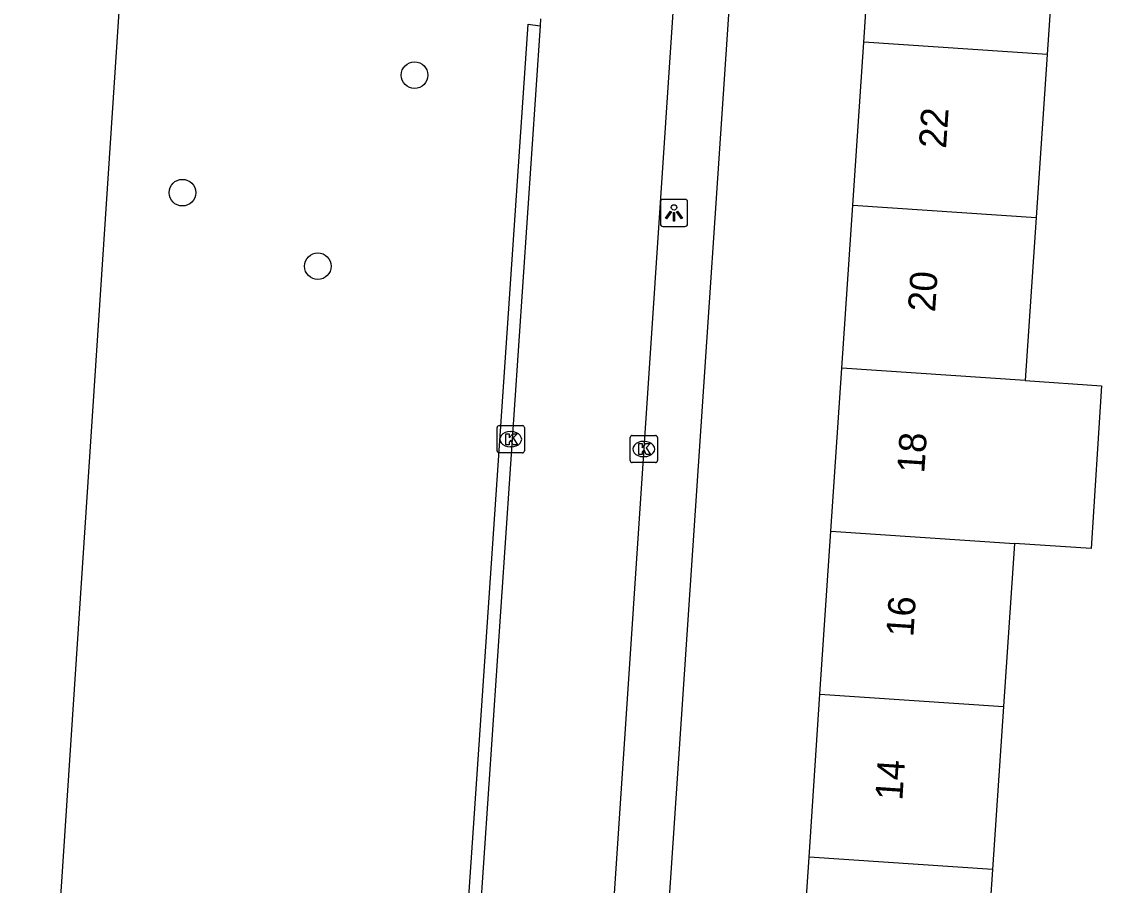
# Model space of a CAD drawing. Extents: x 161848 to 162726, y 385382 to 386521.
# Drawn here: x 161938.07 to 161977.75, y 385931.43 to 385963.18 of the extents above; entities that cross this region are included whole.
import ezdxf

# ---------------------------------------------------------------- set-up
doc = ezdxf.new("R2010")
doc.units = 0
for name, color, linetype in [('IMGEO_Berm_groen', 7, 'Continuous'), ('IMGEO_Boom', 7, 'Continuous'), ('IMGEO_Kolk', 7, 'Continuous'), ('IMGEO_Lichtpunt', 7, 'Continuous'), ('IMGEO_Pand', 7, 'Continuous'), ('IMGEO_Pand_nummerreeks', 7, 'Continuous'), ('IMGEO_Rijbaan_lokaal_open', 7, 'Continuous'), ('IMGEO_Verkeerseiland_open', 7, 'Continuous'), ('IMGEO_Voetpad_open', 7, 'Continuous')]:
    doc.layers.add(name, color=color, linetype=linetype)

msp = doc.modelspace()

# ---------------------------------------------------------------- linework, layer by layer
at = {"layer": 'IMGEO_Berm_groen'}
msp.add_lwpolyline([(161936.046, 385878.605), (161941.769, 385965.23)], dxfattribs=at)
at = {"layer": 'IMGEO_Boom'}
for centre in [(161952.514, 385961.213), (161943.984, 385956.893), (161948.961, 385954.19)]:
    msp.add_circle(centre, 0.489, dxfattribs=at)
at = {"layer": 'IMGEO_Kolk'}
for p, q in [((161955.546, 385947.405), (161955.546, 385948.257)), ((161955.621, 385948.331), (161956.473, 385948.331)), ((161956.034, 385948.111), (161956.059, 385948.111)), ((161956.547, 385948.257), (161956.547, 385947.405)), ((161960.435, 385947.046), (161960.435, 385947.898)), ((161960.51, 385947.972), (161961.362, 385947.972)), ((161960.923, 385947.752), (161960.948, 385947.752)), ((161961.436, 385947.898), (161961.436, 385947.046)), ((161956.473, 385947.331), (161955.621, 385947.331)), ((161956.057, 385947.551), (161956.032, 385947.551)), ((161961.362, 385946.972), (161960.51, 385946.972)), ((161960.946, 385947.192), (161960.921, 385947.192))]:
    msp.add_line(p, q, dxfattribs=at)
for points in [[(161955.546, 385947.405), (161955.546, 385948.257)], [(161955.621, 385948.331), (161956.473, 385948.331)], [(161955.867, 385948.031), (161955.99, 385948.031), (161955.99, 385947.88), (161956.12, 385948.031), (161956.284, 385948.031), (161956.138, 385947.88), (161956.291, 385947.631), (161956.139, 385947.631), (161956.054, 385947.795), (161955.99, 385947.728), (161955.99, 385947.631), (161955.867, 385947.631), (161955.867, 385948.031)], [(161956.547, 385948.257), (161956.547, 385947.405)], [(161960.435, 385947.046), (161960.435, 385947.898)], [(161960.51, 385947.972), (161961.362, 385947.972)], [(161960.756, 385947.672), (161960.879, 385947.672), (161960.879, 385947.521), (161961.009, 385947.672), (161961.173, 385947.672), (161961.027, 385947.521), (161961.18, 385947.272), (161961.028, 385947.272), (161960.943, 385947.436), (161960.879, 385947.369), (161960.879, 385947.272), (161960.756, 385947.272), (161960.756, 385947.672)], [(161961.436, 385947.898), (161961.436, 385947.046)], [(161956.473, 385947.331), (161955.621, 385947.331)], [(161961.362, 385946.972), (161960.51, 385946.972)]]:
    msp.add_lwpolyline(points, dxfattribs=at)
for centre, start, end in [((161955.623, 385948.255), 91.552, 178.448), ((161955.623, 385948.255), 91.552, 178.448), ((161956.471, 385948.255), 1.552, 88.448), ((161956.471, 385948.255), 1.552, 88.448), ((161960.512, 385947.896), 91.552, 178.448), ((161960.512, 385947.896), 91.552, 178.448), ((161961.36, 385947.896), 1.552, 88.448), ((161961.36, 385947.896), 1.552, 88.448), ((161955.623, 385947.407), 181.552, 268.448), ((161955.623, 385947.407), 181.552, 268.448), ((161956.471, 385947.407), 271.552, 358.448), ((161956.471, 385947.407), 271.552, 358.448), ((161960.512, 385947.048), 181.552, 268.448), ((161960.512, 385947.048), 181.552, 268.448), ((161961.36, 385947.048), 271.552, 358.448), ((161961.36, 385947.048), 271.552, 358.448)]:
    msp.add_arc(centre, 0.0765, start, end, dxfattribs=at)
for centre, major_axis, ratio, start_param, end_param in [((161956.033, 385947.831), (-0.387, 0.002), 0.722429, 4.712389, 7.853982), ((161956.058, 385947.831), (-0.39, 0.002), 0.717154, 1.570796, 4.712389), ((161960.922, 385947.472), (-0.387, 0.002), 0.722429, 4.712389, 7.853982), ((161960.947, 385947.472), (-0.39, 0.002), 0.717154, 1.570796, 4.712389)]:
    msp.add_ellipse(centre, major_axis=major_axis, ratio=ratio, start_param=start_param, end_param=end_param, dxfattribs=at)
at = {"layer": 'IMGEO_Lichtpunt'}
for p, q in [((161961.546, 385956.553), (161961.546, 385955.746)), ((161961.546, 385956.553), (161961.546, 385955.746)), ((161962.448, 385956.648), (161961.64, 385956.648)), ((161962.448, 385956.648), (161961.64, 385956.648)), ((161962.542, 385955.746), (161962.542, 385956.553)), ((161962.542, 385955.746), (161962.542, 385956.553)), ((161961.64, 385955.652), (161962.448, 385955.652)), ((161961.64, 385955.652), (161962.448, 385955.652))]:
    msp.add_line(p, q, dxfattribs=at)
for points in [[(161961.92, 385956.217), (161961.959, 385956.189), (161961.771, 385955.927), (161961.733, 385955.954), (161961.92, 385956.217)], [(161962.022, 385956.169), (161962.069, 385956.169), (161962.069, 385955.847), (161962.022, 385955.847), (161962.022, 385956.169)], [(161962.132, 385956.189), (161962.17, 385956.216), (161962.357, 385955.954), (161962.318, 385955.926), (161962.132, 385956.189)]]:
    msp.add_lwpolyline(points, dxfattribs=at)
msp.add_circle((161962.045, 385956.351), 0.0994, dxfattribs=at)
for centre, start, end in [((161961.64, 385956.553), 90, 180), ((161961.64, 385956.553), 90, 180), ((161962.448, 385956.553), 0, 90), ((161962.448, 385956.553), 0, 90), ((161961.64, 385955.746), 180, 270), ((161961.64, 385955.746), 180, 270), ((161962.448, 385955.746), 270, 0), ((161962.448, 385955.746), 270, 360)]:
    msp.add_arc(centre, 0.0946, start, end, dxfattribs=at)
at = {"layer": 'IMGEO_Pand'}
for points in [[(161969.014, 385962.425), (161969.425, 385968.564), (161976.168, 385968.112), (161975.757, 385961.973)], [(161968.612, 385956.434), (161969.014, 385962.425)], [(161975.757, 385961.973), (161969.014, 385962.425)], [(161975.757, 385961.973), (161975.355, 385955.982)], [(161968.21, 385950.442), (161968.612, 385956.434)], [(161968.612, 385956.434), (161975.355, 385955.982)], [(161975.355, 385955.982), (161974.953, 385949.99)], [(161967.809, 385944.451), (161968.21, 385950.442)], [(161974.953, 385949.99), (161968.21, 385950.442)], [(161974.953, 385949.99), (161977.748, 385949.791), (161977.376, 385943.812), (161974.552, 385943.999)], [(161967.407, 385938.459), (161967.809, 385944.451)], [(161967.809, 385944.451), (161974.552, 385943.999)], [(161974.552, 385943.999), (161974.15, 385938.007)], [(161967.006, 385932.468), (161967.407, 385938.459)], [(161967.407, 385938.459), (161974.15, 385938.007)], [(161974.15, 385938.007), (161973.749, 385932.016)], [(161966.604, 385926.476), (161967.006, 385932.468)], [(161973.749, 385932.016), (161967.006, 385932.468)], [(161973.749, 385932.016), (161973.347, 385926.024)]]:
    msp.add_lwpolyline(points, dxfattribs=at)
at = {"layer": 'IMGEO_Rijbaan_lokaal_open'}
for points in [[(161962.333, 385968.495), (161960.348, 385938.653), (161956.869, 385886.598)], [(161957.141, 385963.277), (161957.125, 385963.028)], [(161957.125, 385963.028), (161953.306, 385906.577)]]:
    msp.add_lwpolyline(points, dxfattribs=at)
at = {"layer": 'IMGEO_Verkeerseiland_open'}
msp.add_lwpolyline([(161954.287, 385927.783), (161956.682, 385963.084), (161957.125, 385963.028)], dxfattribs=at)
at = {"layer": 'IMGEO_Voetpad_open'}
msp.add_lwpolyline([(161964.413, 385968.919), (161959.389, 385894.166)], dxfattribs=at)

# ---------------------------------------------------------------- texts
at = {"layer": 'IMGEO_Pand_nummerreeks'}
for s, rotation, p in [('22', 86.1655, (161972.038, 385958.496)), ('20', 86.1655, (161971.635, 385952.488)), ('18', 86.1671, (161971.238, 385946.565)), ('16', 86.1655, (161970.835, 385940.548)), ('14', 86.1655, (161970.432, 385934.535))]:
    msp.add_text(s, height=1, rotation=rotation, dxfattribs=at).set_placement(p)

doc.saveas('drawing.dxf')
